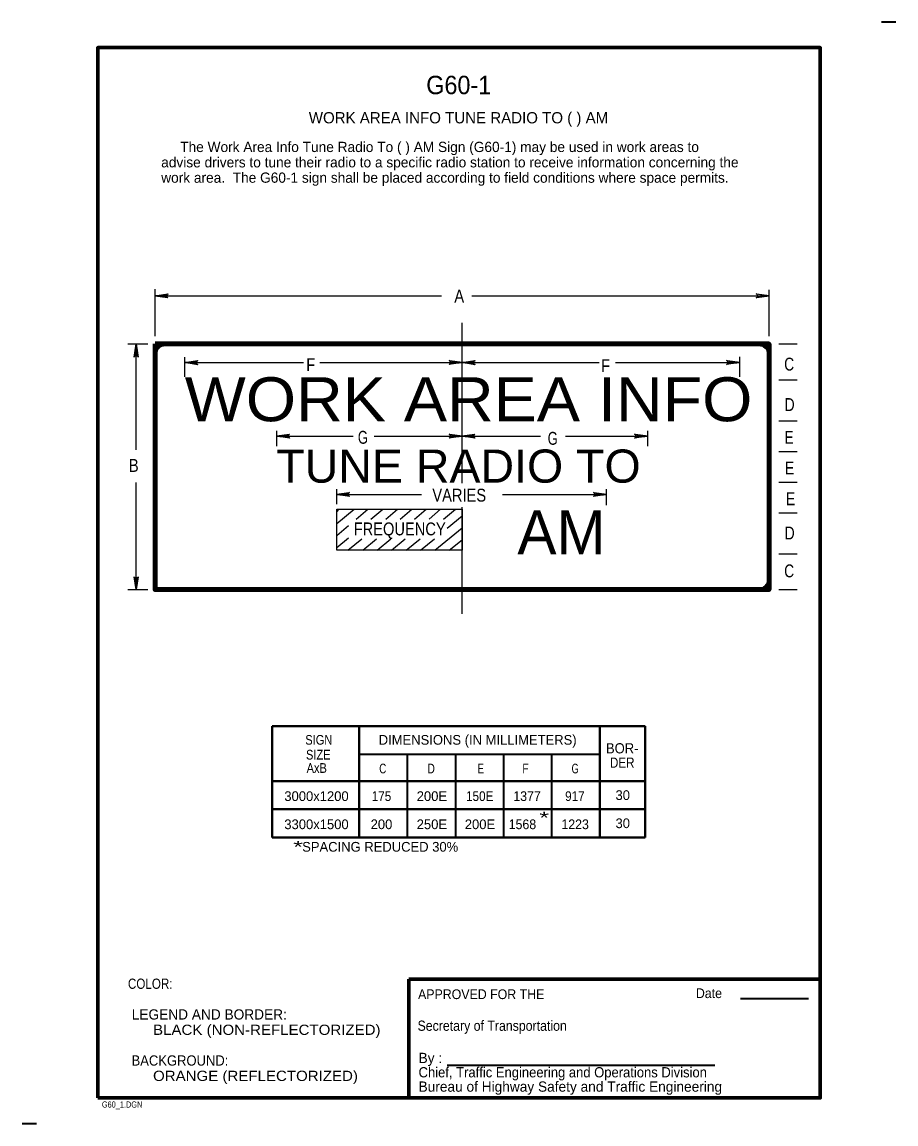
# Model space of a CAD drawing. Extents: x -2.572 to -2.359, y -78.725 to -78.456.
import ezdxf
from ezdxf.enums import TextEntityAlignment as Align

# ---------------------------------------------------------------- set-up
doc = ezdxf.new("R2010")
doc.units = 0
doc.header["$LTSCALE"] = 0.001
doc.linetypes.add('DOT_DASHED', pattern=[7.7, 5, -1.2, 0.3, -1.2])
doc.layers.add('1', color=7, linetype='Continuous', lineweight=25)
doc.layers.add('3', color=7, linetype='Continuous', lineweight=40)

msp = doc.modelspace()

# ---------------------------------------------------------------- linework, layer by layer
at = {"layer": '1', "lineweight": 35}
for p, q in [((-2.358625, -78.456), (-2.362125, -78.456)), ((-2.396625, -78.6945), (-2.38, -78.6945)), ((-2.46825, -78.71075), (-2.402875, -78.71075)), ((-2.568625, -78.725125), (-2.572125, -78.725125))]:
    msp.add_line(p, q, dxfattribs=at)
at = {"layer": '1'}
for p, q in [((-2.539625, -78.53275), (-2.539625, -78.52125)), ((-2.389625, -78.53275), (-2.389625, -78.521375)), ((-2.539625, -78.522875), (-2.469625, -78.522875)), ((-2.46225, -78.522875), (-2.389625, -78.522875)), ((-2.54625, -78.534625), (-2.541375, -78.534625)), ((-2.54425, -78.5605), (-2.54425, -78.534625)), ((-2.38725, -78.534625), (-2.38275, -78.534625)), ((-2.532375, -78.542625), (-2.532375, -78.537875)), ((-2.39675, -78.542625), (-2.39675, -78.53775)), ((-2.532375, -78.539125), (-2.503375, -78.539125)), ((-2.427125, -78.539125), (-2.39675, -78.539125)), ((-2.38725, -78.543375), (-2.38275, -78.543375)), ((-2.38725, -78.553375), (-2.38275, -78.553375)), ((-2.509875, -78.559625), (-2.509875, -78.555875)), ((-2.509875, -78.557125), (-2.49125, -78.557125)), ((-2.439375, -78.557125), (-2.41925, -78.557125)), ((-2.41925, -78.559625), (-2.41925, -78.555875)), ((-2.38725, -78.560875), (-2.38275, -78.560875)), ((-2.54425, -78.594625), (-2.54425, -78.5685)), ((-2.49525, -78.57375), (-2.49525, -78.570125)), ((-2.429375, -78.574), (-2.429375, -78.570125)), ((-2.38725, -78.568375), (-2.38275, -78.568375)), ((-2.49525, -78.571375), (-2.4745, -78.571375)), ((-2.45475, -78.571375), (-2.429375, -78.571375)), ((-2.49525, -78.575625), (-2.494625, -78.575)), ((-2.49525, -78.5785), (-2.491, -78.575)), ((-2.4905, -78.577375), (-2.487625, -78.575)), ((-2.486875, -78.577375), (-2.484, -78.575)), ((-2.48325, -78.577375), (-2.480375, -78.575)), ((-2.47975, -78.577375), (-2.476875, -78.575)), ((-2.47625, -78.577375), (-2.473375, -78.575)), ((-2.472625, -78.577375), (-2.469875, -78.575)), ((-2.469125, -78.577375), (-2.46625, -78.575)), ((-2.38725, -78.575875), (-2.38275, -78.575875)), ((-2.49525, -78.581375), (-2.492375, -78.579)), ((-2.46825, -78.579625), (-2.464625, -78.576625)), ((-2.47125, -78.585), (-2.464625, -78.5795)), ((-2.49525, -78.584375), (-2.492375, -78.582)), ((-2.4925, -78.585), (-2.489125, -78.58225)), ((-2.488875, -78.585), (-2.4855, -78.58225)), ((-2.485375, -78.585), (-2.482, -78.58225)), ((-2.481875, -78.585), (-2.4785, -78.58225)), ((-2.47825, -78.585), (-2.474875, -78.58225)), ((-2.47475, -78.585), (-2.471375, -78.58225)), ((-2.46775, -78.585), (-2.464625, -78.5825)), ((-2.38725, -78.585875), (-2.38275, -78.585875)), ((-2.54625, -78.594625), (-2.541375, -78.594625)), ((-2.38725, -78.594625), (-2.38275, -78.594625))]:
    msp.add_line(p, q, dxfattribs=at)
at = {"layer": '1', "linetype": 'DOT_DASHED'}
for p, q in [((-2.464625, -78.568625), (-2.464625, -78.5295)), ((-2.464625, -78.6005), (-2.464625, -78.5745))]:
    msp.add_line(p, q, dxfattribs=at)
at = {"layer": '1', "lineweight": 70}
for q in [(-2.377125, -78.68975), (-2.477625, -78.71875)]:
    msp.add_line((-2.477625, -78.68975), q, dxfattribs=at)
msp.add_lwpolyline([(-2.553625, -78.71875), (-2.377125, -78.71875), (-2.377125, -78.46225), (-2.553625, -78.46225)], close=True, dxfattribs=at)
at = {"layer": '1'}
for points in [[(-2.536625, -78.52325), (-2.53675, -78.523125), (-2.539625, -78.522875), (-2.536625, -78.52325), (-2.5365, -78.523375), (-2.539625, -78.522875), (-2.53675, -78.52275), (-2.536625, -78.522625), (-2.539625, -78.522875), (-2.5365, -78.522375), (-2.536625, -78.522625)], [(-2.392625, -78.5225), (-2.3925, -78.52275), (-2.389625, -78.522875), (-2.392625, -78.5225), (-2.39275, -78.522375), (-2.389625, -78.522875), (-2.3925, -78.523125), (-2.392625, -78.52325), (-2.389625, -78.522875), (-2.39275, -78.523375), (-2.392625, -78.52325)], [(-2.544625, -78.537625), (-2.544375, -78.5375), (-2.54425, -78.534625), (-2.544625, -78.537625), (-2.54475, -78.537875), (-2.54425, -78.534625), (-2.544125, -78.5375), (-2.543875, -78.537625), (-2.54425, -78.534625), (-2.54375, -78.537875), (-2.543875, -78.537625)], [(-2.529375, -78.5395), (-2.5295, -78.539375), (-2.532375, -78.539125), (-2.529375, -78.5395), (-2.52925, -78.53975), (-2.532375, -78.539125), (-2.5295, -78.539), (-2.529375, -78.538875), (-2.532375, -78.539125), (-2.52925, -78.538625), (-2.529375, -78.538875)], [(-2.467625, -78.53875), (-2.4675, -78.539), (-2.464625, -78.539125), (-2.467625, -78.53875), (-2.46775, -78.538625), (-2.464625, -78.539125), (-2.4675, -78.539375), (-2.467625, -78.5395), (-2.464625, -78.539125), (-2.46775, -78.539625), (-2.467625, -78.5395)], [(-2.461625, -78.5395), (-2.46175, -78.539375), (-2.464625, -78.539125), (-2.461625, -78.5395), (-2.4615, -78.53975), (-2.464625, -78.539125), (-2.46175, -78.539), (-2.461625, -78.538875), (-2.464625, -78.539125), (-2.4615, -78.538625), (-2.461625, -78.538875)], [(-2.39975, -78.53875), (-2.39975, -78.539), (-2.39675, -78.539125), (-2.39975, -78.53875), (-2.4, -78.538625), (-2.39675, -78.539125), (-2.39975, -78.539375), (-2.39975, -78.5395), (-2.39675, -78.539125), (-2.4, -78.539625), (-2.39975, -78.5395)], [(-2.499375, -78.539125), (-2.464625, -78.539125), (-2.431125, -78.539125)], [(-2.506875, -78.5575), (-2.507, -78.55725), (-2.509875, -78.557125), (-2.506875, -78.5575), (-2.50675, -78.557625), (-2.509875, -78.557125), (-2.507, -78.557), (-2.506875, -78.55675), (-2.509875, -78.557125), (-2.50675, -78.556625), (-2.506875, -78.55675)], [(-2.486125, -78.557125), (-2.464625, -78.557125), (-2.4455, -78.557125)], [(-2.467625, -78.55675), (-2.4675, -78.557), (-2.464625, -78.557125), (-2.467625, -78.55675), (-2.46775, -78.556625), (-2.464625, -78.557125), (-2.4675, -78.55725), (-2.467625, -78.5575), (-2.464625, -78.557125), (-2.46775, -78.557625), (-2.467625, -78.5575)], [(-2.461625, -78.5575), (-2.46175, -78.55725), (-2.464625, -78.557125), (-2.461625, -78.5575), (-2.4615, -78.557625), (-2.464625, -78.557125), (-2.46175, -78.557), (-2.461625, -78.55675), (-2.464625, -78.557125), (-2.4615, -78.556625), (-2.461625, -78.55675)], [(-2.42225, -78.55675), (-2.42225, -78.557), (-2.41925, -78.557125), (-2.42225, -78.55675), (-2.4225, -78.556625), (-2.41925, -78.557125), (-2.42225, -78.55725), (-2.42225, -78.5575), (-2.41925, -78.557125), (-2.4225, -78.557625), (-2.42225, -78.5575)], [(-2.49225, -78.57175), (-2.492375, -78.571625), (-2.49525, -78.571375), (-2.49225, -78.57175), (-2.492125, -78.571875), (-2.49525, -78.571375), (-2.492375, -78.57125), (-2.49225, -78.571), (-2.49525, -78.571375), (-2.492125, -78.570875), (-2.49225, -78.571)], [(-2.432375, -78.571), (-2.43225, -78.57125), (-2.429375, -78.571375), (-2.432375, -78.571), (-2.4325, -78.570875), (-2.429375, -78.571375), (-2.43225, -78.5715), (-2.432375, -78.57175), (-2.429375, -78.571375), (-2.4325, -78.571875), (-2.432375, -78.57175)], [(-2.543875, -78.591625), (-2.544125, -78.59175), (-2.54425, -78.594625), (-2.543875, -78.591625), (-2.54375, -78.5915), (-2.54425, -78.594625), (-2.544375, -78.59175), (-2.544625, -78.591625), (-2.54425, -78.594625), (-2.54475, -78.5915), (-2.544625, -78.591625)]]:
    msp.add_lwpolyline(points, dxfattribs=at)
at = {"layer": '1', "lineweight": 106}
msp.add_lwpolyline([(-2.539625, -78.534625), (-2.389625, -78.534625), (-2.389625, -78.594625), (-2.539625, -78.594625)], close=True, dxfattribs=at)
at = {"layer": '1'}
msp.add_lwpolyline([(-2.49525, -78.575), (-2.464625, -78.575), (-2.464625, -78.585), (-2.49525, -78.585)], close=True, dxfattribs=at)
at = {"layer": '1', "lineweight": 80}
for centre, start, end in [((-2.537104, -78.537169), 90, 180), ((-2.392104, -78.537169), 0, 90), ((-2.392104, -78.592169), 270, 0)]:
    msp.add_arc(centre, 0.0025, start, end, dxfattribs=at)
at = {"layer": '3'}
for p, q in [((-2.511, -78.628), (-2.419875, -78.628)), ((-2.511, -78.628), (-2.511, -78.655125)), ((-2.48975, -78.628), (-2.48975, -78.655125)), ((-2.431, -78.628), (-2.431, -78.655125)), ((-2.419875, -78.628), (-2.419875, -78.655125)), ((-2.511, -78.641375), (-2.419875, -78.641375)), ((-2.511, -78.64825), (-2.419875, -78.64825)), ((-2.511, -78.655125), (-2.419875, -78.655125))]:
    msp.add_line(p, q, dxfattribs=at)
at = {"layer": '3', "lineweight": 35}
for p, q in [((-2.431, -78.634875), (-2.48975, -78.634875)), ((-2.478, -78.634875), (-2.478, -78.655125)), ((-2.46625, -78.634875), (-2.46625, -78.655125)), ((-2.46625, -78.634875), (-2.46625, -78.64825)), ((-2.4545, -78.634875), (-2.4545, -78.655125)), ((-2.44275, -78.634875), (-2.44275, -78.655125))]:
    msp.add_line(p, q, dxfattribs=at)

# ---------------------------------------------------------------- texts
at = {"layer": '1'}
for s, height, width, p in [('G60-1', 0.0045, 0.95, (-2.465438, -78.473625)), ('*', 0.00288, 1.6, (-2.444562, -78.65175)), ('*', 0.00288, 1.6, (-2.504688, -78.658875))]:
    msp.add_text(s, height=height, dxfattribs=dict(at, width=width)).set_placement(p, align=Align.CENTER)
msp.add_text('WORK AREA INFO TUNE RADIO TO ( ) AM', height=0.00275, dxfattribs=at).set_placement((-2.4655, -78.48075), align=Align.CENTER)
for s, width, p in [('A', 0.85, (-2.464125, -78.5245)), ('F', 0.85, (-2.5005, -78.54125)), ('F', 0.85, (-2.4285, -78.5415)), ('C', 0.8, (-2.3835, -78.541125)), ('D', 0.8, (-2.383375, -78.551)), ('G', 0.75, (-2.487625, -78.559)), ('G', 0.75, (-2.44125, -78.55925)), ('E', 0.8, (-2.383625, -78.559)), ('B', 0.85, (-2.543625, -78.565875)), ('E', 0.8, (-2.3835, -78.5665)), ('VARIES', 0.85, (-2.45875, -78.573125)), ('E', 0.8, (-2.38325, -78.574)), ('FREQUENCY', 0.85, (-2.468625, -78.581375)), ('D', 0.8, (-2.383375, -78.582375)), ('C', 0.8, (-2.3835, -78.591625))]:
    msp.add_text(s, height=0.00315, dxfattribs=dict(at, width=width)).set_placement(p, align=Align.RIGHT)
for s, height, width, p in [('WORK AREA INFO', 0.01074, 1.1, (-2.532375, -78.5535)), ('TUNE RADIO TO', 0.008093, 1.05, (-2.51, -78.5685)), ('COLOR:', 0.0025, 0.85, (-2.54625, -78.692125)), ('Date ', 0.002375, 0.95, (-2.4075, -78.694375)), ('APPROVED FOR THE', 0.002375, 0.95, (-2.475375, -78.694625)), ('Secretary of Transportation', 0.0025, 0.9, (-2.4755, -78.702375)), ('      BLACK (NON-REFLECTORIZED)', 0.0025, 1.1, (-2.54625, -78.703375)), (' BACKGROUND:', 0.0025, 0.95, (-2.54625, -78.710875)), ('      ORANGE (REFLECTORIZED)', 0.0025, 1.1, (-2.54625, -78.714625)), ('Chief, Traffic Engineering and Operations Division', 0.0025, 0.95, (-2.47525, -78.71375)), ('G60_1.DGN', 0.0015, 0.75, (-2.552625, -78.721125))]:
    msp.add_text(s, height=height, dxfattribs=dict(at, width=width)).set_placement(p)
for s, height, p in [('AM', 0.01074, (-2.451125, -78.586)), (' LEGEND AND BORDER:', 0.0025, (-2.54625, -78.699625)), ('By :', 0.0025, (-2.47525, -78.71025)), ('Bureau of Highway Safety and Traffic Engineering', 0.0025, (-2.47525, -78.71725))]:
    msp.add_text(s, height=height, dxfattribs=at).set_placement(p)
at = {"layer": '3'}
for s, p in [('     The Work Area Info Tune Radio To ( ) AM Sign (G60-1) may be used in work areas to', (-2.538125, -78.48775)), ('advise drivers to tune their radio to a specific radio station to receive information concerning the', (-2.538125, -78.4915)), ('work area.  The G60-1 sign shall be placed according to field conditions where space permits.', (-2.538125, -78.49525))]:
    msp.add_text(s, height=0.0025, dxfattribs=at).set_placement(p)
for s, height, width, p in [('SIGN', 0.002375, 0.85, (-2.499625, -78.6325)), ('BOR-', 0.0025, 0.95, (-2.4255, -78.634625)), ('SIZE', 0.002375, 0.85, (-2.49975, -78.636125)), ('DER', 0.0025, 0.85, (-2.4255, -78.638125)), ('AxB', 0.002375, 0.85, (-2.500125, -78.639375)), ('C', 0.002375, 0.75, (-2.484, -78.6395)), ('D', 0.002375, 0.8, (-2.472187, -78.6395)), ('E', 0.002375, 0.75, (-2.460063, -78.6395)), ('F', 0.002375, 0.8, (-2.449125, -78.6395)), ('G', 0.002375, 0.7, (-2.437, -78.6395)), ('175', 0.002375, 0.9, (-2.484313, -78.64625)), ('150E', 0.002375, 0.9, (-2.460313, -78.64625)), ('1377', 0.002375, 0.95, (-2.44875, -78.64625)), ('917', 0.002375, 0.9, (-2.437063, -78.64625)), ('1568', 0.002375, 0.95, (-2.449875, -78.653125)), ('1223', 0.002375, 0.95, (-2.437, -78.653125))]:
    msp.add_text(s, height=height, dxfattribs=dict(at, width=width)).set_placement(p, align=Align.CENTER)
for s, p in [('DIMENSIONS (IN MILLIMETERS)', (-2.460812, -78.6325)), ('30', (-2.425375, -78.646)), ('3000x1200', (-2.500188, -78.64625)), ('200E', (-2.472, -78.64625)), ('3300x1500', (-2.500188, -78.653125)), ('200', (-2.484313, -78.653125)), ('250E', (-2.472, -78.653125)), ('200E', (-2.46025, -78.653125)), ('30', (-2.425375, -78.652875)), ('SPACING REDUCED 30%', (-2.484625, -78.658625))]:
    msp.add_text(s, height=0.002375, dxfattribs=at).set_placement(p, align=Align.CENTER)

doc.saveas('drawing.dxf')
